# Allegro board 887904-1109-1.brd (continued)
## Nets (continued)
D20604: D206.04
D20605: D206.05
D20606: D206.06
D20607: D206.07
D20608: D206.08
D20609: D206.09
D20610: D206.10
D20611: D206.11
D20612: D206.12
D20613: D206.13
D20614: D206.14
D20615: D206.15
D20616: D206.16
D20701: D207.01
D20702: D207.02
D20703: D207.03
D20704: D207.04
D20705: D207.05
D20706: D207.06
D20707: D207.07
D20708: D207.08
D20709: D207.09
D20710: D207.10
D20711: D207.11
D20712: D207.12
D20713: D207.13
D20714: D207.14
D20715: D207.15
D20716: D207.16
D20801: D208.01
D20802: D208.02
D20803: D208.03
D20804: D208.04
D20805: D208.05
D20806: D208.06
D20807: D208.07
D20808: D208.08
D20809: D208.09
D20810: D208.10
D20811: D208.11
D20812: D208.12
D20813: D208.13
D20814: D208.14
D20815: D208.15
D20816: D208.16
D20901: D209.01
D20902: D209.02
D20903: D209.03
D20904: D209.04
D20905: D209.05
D20906: D209.06
D20907: D209.07
D20908: D209.08
D20909: D209.09
D20910: D209.10
D20911: D209.11
D20912: D209.12
D20913: D209.13
D20914: D209.14
D20915: D209.15
D20916: D209.16
D21001: D210.01
D21002: D210.02
D21003: D210.03
D21004: D210.04
D21005: D210.05
D21006: D210.06
D21007: D210.07
D21008: D210.08
D21009: D210.09
D21010: D210.10
D21011: D210.11
D21012: D210.12
D21013: D210.13
D21014: D210.14
D21015: D210.15
D21016: D210.16
D21101: D211.01
D21102: D211.02
D21103: D211.03
D21104: D211.04
D21105: D211.05
D21106: D211.06
D21107: D211.07
D21108: D211.08
D21109: D211.09
D21110: D211.10
D21111: D211.11
D21112: D211.12
D21113: D211.13
D21114: D211.14
D21115: D211.15
D21116: D211.16
D21201: D212.01
D21202: D212.02
D21203: D212.03
D21204: D212.04
D21205: D212.05
D21206: D212.06
D21207: D212.07
D21208: D212.08
D21209: D212.09
D21210: D212.10
D21211: D212.11
D21212: D212.12
D21213: D212.13
D21214: D212.14
D21215: D212.15
D21216: D212.16
D21301: D213.01
D21302: D213.02
D21303: D213.03
D21304: D213.04
D21305: D213.05
D21306: D213.06
D21307: D213.07
D21308: D213.08
D21309: D213.09
D21310: D213.10
D21311: D213.11
D21312: D213.12
D21313: D213.13
D21314: D213.14
D21315: D213.15
D21316: D213.16
D21401: D214.01
D21402: D214.02
D21403: D214.03
D21404: D214.04
D21405: D214.05
D21406: D214.06
D21407: D214.07
D21408: D214.08
D21409: D214.09
D21410: D214.10
D21411: D214.11
D21412: D214.12
D21413: D214.13
D21414: D214.14
D21415: D214.15
D21416: D214.16
D21501: D215.01
D21502: D215.02
D21503: D215.03
D21504: D215.04
D21505: D215.05
D21506: D215.06
D21507: D215.07
D21508: D215.08
D21509: D215.09
D21510: D215.10
D21511: D215.11
D21512: D215.12
D21513: D215.13
D21514: D215.14
D21515: D215.15
D21516: D215.16
D21601: D216.01
D21602: D216.02
D21603: D216.03
D21604: D216.04
D21605: D216.05
D21606: D216.06
D21607: D216.07
D21608: D216.08
D21609: D216.09
D21610: D216.10
D21611: D216.11
D21612: D216.12
D21613: D216.13
D21614: D216.14
D21615: D216.15
D21616: D216.16
D21701: D217.01
D21702: D217.02
D21703: D217.03
D21704: D217.04
D21705: D217.05
D21706: D217.06
D21707: D217.07
D21708: D217.08
D21709: D217.09
D21710: D217.10
D21711: D217.11
D21712: D217.12
D21713: D217.13
D21714: D217.14
D21715: D217.15
D21716: D217.16
D21801: D218.01
D21802: D218.02
D21803: D218.03
D21804: D218.04
D21805: D218.05
D21806: D218.06
D21807: D218.07
D21808: D218.08
D21809: D218.09
D21810: D218.10
D21811: D218.11
D21812: D218.12
D21813: D218.13
D21814: D218.14
D21815: D218.15
D21816: D218.16
D21901: D219.01
D21902: D219.02
D21903: D219.03
D21904: D219.04
D21905: D219.05
D21906: D219.06
D21907: D219.07
D21908: D219.08
D21909: D219.09
D21910: D219.10
D21911: D219.11
D21912: D219.12
D21913: D219.13
D21914: D219.14
D21915: D219.15
D21916: D219.16
D22001: D220.01
D22002: D220.02
D22003: D220.03
D22004: D220.04
D22005: D220.05
D22006: D220.06
D22007: D220.07
D22008: D220.08
D22009: D220.09
D22010: D220.10
D22011: D220.11
D22012: D220.12
D22013: D220.13
D22014: D220.14
D22015: D220.15
D22016: D220.16
D22101: D221.01
D22102: D221.02
D22103: D221.03
D22104: D221.04
D22105: D221.05
D22106: D221.06
D22107: D221.07
D22108: D221.08
D22109: D221.09
D22110: D221.10
D22111: D221.11
D22112: D221.12
D22113: D221.13
D22114: D221.14
D22115: D221.15
D22116: D221.16
D22201: D222.01
D22202: D222.02
D22203: D222.03
D22204: D222.04
D22205: D222.05
D22206: D222.06
D22207: D222.07
D22208: D222.08
D22209: D222.09
D22210: D222.10
D22211: D222.11
D22212: D222.12
D22213: D222.13
D22214: D222.14
D22215: D222.15
D22216: D222.16
D22301: D223.01
D22302: D223.02
D22303: D223.03
D22304: D223.04
D22305: D223.05
D22306: D223.06
D22307: D223.07
D22308: D223.08
D22309: D223.09
D22310: D223.10
D22311: D223.11
D22312: D223.12
D22313: D223.13
D22314: D223.14
D22315: D223.15
D22316: D223.16
D22401: D224.01
D22402: D224.02
D22403: D224.03
D22404: D224.04
D22405: D224.05
D22406: D224.06
D22407: D224.07
D22408: D224.08
D22409: D224.09
D22410: D224.10
D22411: D224.11
D22412: D224.12
D22413: D224.13
D22414: D224.14
D22415: D224.15
D22416: D224.16
D30101: D301.01
D30102: D301.02
D30103: D301.03
D30104: D301.04
D30105: D301.05
D30106: D301.06
D30107: D301.07
D30108: D301.08
D30109: D301.09
D30110: D301.10
D30111: D301.11
D30112: D301.12
D30113: D301.13
D30114: D301.14
D30115: D301.15
D30116: D301.16
D30201: D302.01
D30202: D302.02
D30203: D302.03
D30204: D302.04
D30205: D302.05
D30206: D302.06
D30207: D302.07
D30208: D302.08
D30209: D302.09
D30210: D302.10
D30211: D302.11
D30212: D302.12
D30213: D302.13
D30214: D302.14
D30215: D302.15
D30216: D302.16
D30501: D305.01
D30502: D305.02
D30503: D305.03
D30504: D305.04
D30505: D305.05
D30506: D305.06
D30507: D305.07
D30508: D305.08
D30509: D305.09
D30510: D305.10
D30511: D305.11
D30512: D305.12
D30513: D305.13
D30514: D305.14
D30515: D305.15
D30516: D305.16
D30601: D306.01
D30602: D306.02
D30603: D306.03
D30604: D306.04
D30605: D306.05
D30606: D306.06
D30607: D306.07
D30608: D306.08
D30609: D306.09
D30610: D306.10
D30611: D306.11
D30612: D306.12
D30613: D306.13
D30614: D306.14
D30615: D306.15
D30616: D306.16
D31701: D317.01
D31702: D317.02
D31703: D317.03
D31704: D317.04
D31705: D317.05
D31706: D317.06
D31707: D317.07
D31708: D317.08
D31709: D317.09
D31710: D317.10
D31711: D317.11
D31712: D317.12
D31713: D317.13
D31714: D317.14
D31715: D317.15
D31716: D317.16
D31801: D318.01
D31802: D318.02
D31803: D318.03
D31804: D318.04
D31805: D318.05
D31806: D318.06
D31807: D318.07
D31808: D318.08
D31809: D318.09
D31810: D318.10
D31811: D318.11
D31812: D318.12
D31813: D318.13
D31814: D318.14
D31815: D318.15
D31816: D318.16
D32101: D321.01
D32102: D321.02
D32103: D321.03
D32104: D321.04
D32105: D321.05
D32106: D321.06
D32107: D321.07
D32108: D321.08
D32109: D321.09
D32110: D321.10
D32111: D321.11
D32112: D321.12
D32113: D321.13
D32114: D321.14
D32115: D321.15
D32116: D321.16
D32201: D322.01
D32202: D322.02
D32203: D322.03
D32204: D322.04
D32205: D322.05
D32206: D322.06
D32207: D322.07
D32208: D322.08
D32209: D322.09
D32210: D322.10
D32211: D322.11
D32212: D322.12
D32213: D322.13
D32214: D322.14
D32215: D322.15
D32216: D322.16
DPS1_C1: DPS1.C01
DPS1_C5: DPS1.C05
DPS1_C11: DPS1.C11
DPS1_C15: DPS1.C15
DPS2_C1: DPS2.C01
DPS2_C5: DPS2.C05
DPS2_C11: DPS2.C11
DPS2_C15: DPS2.C15
DPS3_C1: DPS3.C01
DPS3_C5: DPS3.C05
DPS3_C11: DPS3.C11
DPS3_C15: DPS3.C15
DPS8_C1: DPS8.C01
DPS8_C5: DPS8.C05
DPS8_C11: DPS8.C11
DPS8_C15: DPS8.C15
MSDPS1_1F: DPS1.C03
MSDPS1_1GRD: DPS1.B02
MSDPS1_1GS: DPS1.A02
MSDPS1_1S: DPS1.C02
MSDPS1_2F: DPS1.C07
MSDPS1_2GRD: DPS1.B06
MSDPS1_2GS: DPS1.A06
MSDPS1_2S: DPS1.C06
MSDPS1_3F: DPS1.C13
MSDPS1_3GRD: DPS1.B12
MSDPS1_3GS: DPS1.A12
MSDPS1_3S: DPS1.C12
MSDPS1_4F: DPS1.C17
MSDPS1_4GRD: DPS1.B16
MSDPS1_4GS: DPS1.A16
MSDPS1_4S: DPS1.C16
MSDPS1_5F: DPS1.A03
MSDPS1_5GS: DPS1.B01
MSDPS1_5S: DPS1.B03
MSDPS1_6F: DPS1.A07
MSDPS1_6GS: DPS1.B05
MSDPS1_6S: DPS1.B07
MSDPS1_7F: DPS1.A13
MSDPS1_7GS: DPS1.B11
MSDPS1_7S: DPS1.B13
MSDPS1_8F: DPS1.A17
MSDPS1_8GS: DPS1.B15
MSDPS1_8S: DPS1.B17
MSDPS1_TR+: DPS1.A09 DPS2.A09 DPS3.A09 DPS8.A09 SB11.1
MSDPS1_TRVB-: DPS1.B09 SB1.2
MSDPS1_VB+: DPS1.C09 DPS2.C09 DPS3.C09 DPS8.C09 SB12.1
MSDPS2_1F: DPS2.C03
MSDPS2_1GRD: DPS2.B02
MSDPS2_1GS: DPS2.A02
MSDPS2_1S: DPS2.C02
MSDPS2_2F: DPS2.C07
MSDPS2_2GRD: DPS2.B06
MSDPS2_2GS: DPS2.A06
MSDPS2_2S: DPS2.C06
MSDPS2_3F: DPS2.C13
MSDPS2_3GRD: DPS2.B12
MSDPS2_3GS: DPS2.A12
MSDPS2_3S: DPS2.C12
MSDPS2_4F: DPS2.C17
MSDPS2_4GRD: DPS2.B16
MSDPS2_4GS: DPS2.A16
MSDPS2_4S: DPS2.C16
MSDPS2_5F: DPS2.A03
MSDPS2_5GS: DPS2.B01
MSDPS2_5S: DPS2.B03
MSDPS2_6F: DPS2.A07
MSDPS2_6GS: DPS2.B05
MSDPS2_6S: DPS2.B07
MSDPS2_7F: DPS2.A13
MSDPS2_7GS: DPS2.B11
MSDPS2_7S: DPS2.B13
MSDPS2_8F: DPS2.A17
MSDPS2_8GS: DPS2.B15
MSDPS2_8S: DPS2.B17
MSDPS2_TRVB-: DPS2.B09 SB2.2
MSDPS3_1F: DPS3.C03
MSDPS3_1GRD: DPS3.B02
MSDPS3_1GS: DPS3.A02
MSDPS3_1S: DPS3.C02
MSDPS3_2F: DPS3.C07
MSDPS3_2GRD: DPS3.B06
MSDPS3_2GS: DPS3.A06
MSDPS3_2S: DPS3.C06
MSDPS3_3F: DPS3.C13
MSDPS3_3GRD: DPS3.B12
MSDPS3_3GS: DPS3.A12
MSDPS3_3S: DPS3.C12
MSDPS3_4F: DPS3.C17
MSDPS3_4GRD: DPS3.B16
MSDPS3_4GS: DPS3.A16
MSDPS3_4S: DPS3.C16
MSDPS3_5F: DPS3.A03
MSDPS3_5GS: DPS3.B01
MSDPS3_5S: DPS3.B03
MSDPS3_6F: DPS3.A07
MSDPS3_6GS: DPS3.B05
MSDPS3_6S: DPS3.B07
MSDPS3_7F: DPS3.A13
MSDPS3_7GS: DPS3.B11
MSDPS3_7S: DPS3.B13
MSDPS3_8F: DPS3.A17
MSDPS3_8GS: DPS3.B15
MSDPS3_8S: DPS3.B17
MSDPS3_TRVB-: DPS3.B09 SB3.2
MSDPS8_1F: DPS8.C03
MSDPS8_1GRD: DPS8.B02
MSDPS8_1GS: DPS8.A02
MSDPS8_1S: DPS8.C02
MSDPS8_2F: DPS8.C07
MSDPS8_2GRD: DPS8.B06
MSDPS8_2GS: DPS8.A06
MSDPS8_2S: DPS8.C06
MSDPS8_3F: DPS8.C13
MSDPS8_3GRD: DPS8.B12
MSDPS8_3GS: DPS8.A12
MSDPS8_3S: DPS8.C12
MSDPS8_4F: DPS8.C17
MSDPS8_4GRD: DPS8.B16
MSDPS8_4GS: DPS8.A16
MSDPS8_4S: DPS8.C16
MSDPS8_5F: DPS8.A03
MSDPS8_5GS: DPS8.B01
MSDPS8_5S: DPS8.B03
MSDPS8_6F: DPS8.A07
MSDPS8_6GS: DPS8.B05
MSDPS8_6S: DPS8.B07
MSDPS8_7F: DPS8.A13
MSDPS8_7GS: DPS8.B11
MSDPS8_7S: DPS8.B13
MSDPS8_8F: DPS8.A17
MSDPS8_8GS: DPS8.B15
MSDPS8_8S: DPS8.B17
MSDPS8_TRVB-: DPS8.B09 SB8.2
S1_AUX1+: K9.5 R162.1
S1_AUX1-: K9.4 R161.1
S1_AUX2+: C54.2 R52.1 R54.2 R162.2
S1_AUX2-: C53.2 R51.2 R53.2 R161.2
S1_AUX+: K9.6 K50.6 SITE1.D14(AUX_P)
S1_AUX-: K9.3 K50.3 SITE1.E14(AUX_N)
S1_AUX_100DCH001+: K9.7
S1_AUX_100DCH001-: K9.2
S1_AUX_100DCH003+: C54.1
S1_AUX_100DCH003-: C53.1
S1_DCH005: SITE1.A14(HPD)
S1_DCH006: K10.3 SITE1.A1(RESET)
S1_DCH007: SITE1.B15(BIST)
S1_DCH009: SITE1.C15(CABC_EN)
S1_DCH010: SITE1.A15(PWMI)
S1_DCH011: SITE1.E3(PWMO)
S1_DCH012: K28.6 SITE1.C1(I2C_SDA)
S1_DCH013: K28.3 SITE1.D1(I2C_SCL)
S1_DCH014: K48.2
S1_DCH015: SITE1.E5(GPIO1)
S1_DCH016: SITE1.D5(GPIO2)
S1_DCH017: SITE1.D6(GPIO3)
S1_DCH018: SITE1.D7(GPIO4)
S1_DCH019: SITE1.D8(GPIO5)
S1_DCH020: SITE1.E6(GPIO6)
S1_DCH021: SITE1.D3(GPIO7)
S1_DCH022: SITE1.E4(GPIO8)
S1_DCH023: SITE1.C2(GPIO9)
S1_DCH024: SITE1.D15(GPIO10)
S1_DCH025: SITE1.B1(STV1)
S1_DCH026: SITE1.D2(STV2)
S1_DCH027: SITE1.B2(CPV)
S1_DCH028: SITE1.E1(OE1)
S1_DCH029: SITE1.E2(OE2)
S1_DCH030: SITE1.A3(XSTB)
S1_DCH031: SITE1.A2(SD_LOCK)
S1_DCH032: R200.2
S1_DCH033: R201.2
S1_DCH034: R202.2
S1_DCH035: R203.2
S1_DCH036: R204.2
S1_DCH037: R205.2
S1_DCH038: R206.2
S1_DCH039: R207.2
S1_DCH040: R208.2
S1_DCH041: R209.2
S1_DCH42: K15.2
S1_DCH43: K15.7
S1_DCH44: K14.2
S1_DCH45: K14.7
S1_DPS_F01: C67.1 CA1.1 CC1.1 CC2.1 CC3.1 CC4.1 CD1.1 CD2.1 CD3.1 CD4.1 K55.4 R200.1 SH1.2 SITE1.C4(VDD_CORE_09[1]) SITE1.C8(VDD_CORE_09[2]) SITE1.C9(VDD_CORE_09[3]) SITE1.C10(VDD_CORE_09[4]) TP_VDD09_CORE.1(TP)
S1_DPS_F03: C71.1 CA2.1 CC5.1 CC6.1 CC7.1 CD5.1 CD6.1 CD7.1 K56.4 R55.2 R201.1 SH3.2 SITE1.C5(VDD_IO_18[2]) SITE1.C6(VDD_IO_18[3]) SITE1.C11(VDD_IO_18[1]) TP_VDDIO_18.1(TP)
S1_DPS_F04: C73.1 CA3.1 CC8.1 CD8.1 K57.9 R202.1 SH6.2 SITE1.A5(VDD_TX_09_HDO) TP_VDD_TX_09_HDO.1(TP)
S1_DPS_F05: C75.1 CA4.1 CC9.1 CD9.1 K58.4 R203.1 SH7.2 SITE1.C7(VDD_TXPST_09) TP_VDD_TXPST_09.1(TP)
S1_DPS_F06: C77.1 CA5.1 CC10.1 CD10.1 K58.9 R204.1 SH10.2 SITE1.A4(VDD_TX_09) TP_VDD_TX_09.1(TP)
S1_DPS_F07: C79.1 CA6.1 CC11.1 CD11.1 K59.4 R205.1 SH12.2 SITE1.C14(VDDRX_AUX_09) TP_VDDRX_AUX.1(TP)
S1_DPS_F08: C81.1 CA7.1 CC12.1 CD12.1 K56.9 R206.1 SH14.2 SITE1.E15(VDDRX_09) TP_VDDRX_09.1(TP)
S1_DPS_F09: C83.1 CA8.1 CC13.1 CD13.1 K59.9 R207.1 SH16.2 SITE1.B3(VDD_PLL_09) TP_VDD_PLL_09.1(TP)
S1_DPS_F10: C85.1 CA9.1 CC14.1 CD14.1 K55.9 R208.1 SH18.2 SITE1.B14(VDD_IOB_18_BOOST) TP_VDD_IOB_18_BOOST.1(TP)
S1_DPS_F11: C87.1 CA10.1 CC15.1 CD15.1 K57.4 R209.1 SH20.2 SITE1.C3(VDD_IOB_18_POR) TP_VDD_IOB_18_POR.1(TP)
S1_DPS_F12: CA12.1 R52.2 R53.1 SH22.2 TP_S1_V25.1(TP)
S1_DPS_F13: CA13.1 K48.4 SH24.2 TP_VDD_EFUSE_POWER.1(TP)
S1_DPS_F14: C1.1 CA14.1 R69.1 R70.1 R71.1 R72.1 R73.1 R74.1 R147.2 R148.2 SH26.2 TP_VDD_EFUSE_POWER1.1(TP) U5.8(VCC)
S1_DPS_FS01: SH1.1
S1_DPS_FS03: SH3.1
S1_DPS_FS04: SH6.1
S1_DPS_FS05: SH7.1
S1_DPS_FS06: SH10.1
S1_DPS_FS07: SH12.1
S1_DPS_FS08: SH14.1
S1_DPS_FS09: SH16.1
S1_DPS_FS10: SH18.1
S1_DPS_FS11: SH20.1
S1_DPS_FS12: SH22.1
S1_DPS_FS13: SH24.1
S1_DPS_FS14: SH26.1
S1_DPS_GS01: SH2.1
S1_DPS_GS03: SH4.1
S1_DPS_GS04: SH5.1
S1_DPS_GS05: SH8.1
S1_DPS_GS06: SH9.1
S1_DPS_GS07: SH11.1
S1_DPS_GS08: SH13.1
S1_DPS_GS09: SH15.1
S1_DPS_GS10: SH17.1
S1_DPS_GS11: SH19.1
S1_DPS_GS12: SH21.1
S1_DPS_GS13: SH23.1
S1_DPS_GS14: SH25.1
S1_RLY01: K9.8(V-)
S1_RLY02: K50.8(V-)
S1_RLY03: K10.8(V-)
S1_RLY04: K48.8(V-)
S1_RLY08: K54.8(V-)
S1_RLY09: K61.8(V-)
S1_RLY20: K55.12(V-)
S1_RLY22: K57.12(V-)
S1_RLY24: K59.12(V-)
S1_RLY27: K15.8(V-)
S1_RLY43: K60.8(V-)
S1_RLY44: K62.8(V-)
S1_RLY45: K14.8(V-)
S1_RLY46: K28.8(V-)
S1_RLY47: K56.12(V-)
S1_RLY48: K58.12(V-)
S1_ROM_SPI_CS: K15.6 SITE1.E7(ROM_SPI_CS)
S1_ROM_SPI_SCK: K15.3 SITE1.E8(ROM_SPI_SCK)
S1_ROM_SPI_SDI: K14.6 SITE1.E9(ROM_SPI_SDI)
S1_ROM_SPI_SDO: K14.3 SITE1.D9(ROM_SPI_SDO)
S1_RX_85DCH00+: SITE1.E10(RX_N0)
S1_RX_85DCH00-: SITE1.D10(RX_P0)
S1_RX_85DCH01+: SITE1.E11(RX_N1)
S1_RX_85DCH01-: SITE1.D11(RX_P1)
S1_RX_85DCH02+: SITE1.D12(RX_N2)
S1_RX_85DCH02-: SITE1.E12(RX_P2)
S1_RX_85DCH03+: SITE1.D13(RX_N3)
S1_RX_85DCH03-: SITE1.E13(RX_P3)
S1_SPI_1_CSN: K15.5 R69.2 U5.1(CS#)
S1_SPI_1_SCK: K15.4 R73.2 U5.6(SCLK)
S1_SPI_1_SDI: K14.5 R70.2 U5.2(SO)
S1_SPI_1_SDO: K14.4 R74.2 U5.5(SI)
S1_TEST: K48.3 SITE1.D4(TEST)
S1_TX_100DCH0_N: R11.1 SITE1.A13(TX0_N)
S1_TX_100DCH0_P: R12.2 SITE1.B13(TX0_P)
S1_TX_100DCH1_N: R13.1 SITE1.B12(TX1_N)
S1_TX_100DCH1_P: R14.2 SITE1.A12(TX1_P)
S1_TX_100DCH2_N: R15.1 SITE1.B11(TX2_N)
S1_TX_100DCH2_P: R16.2 SITE1.A11(TX2_P)
S1_TX_100DCH3_N: R17.1 SITE1.B10(TX3_N)
S1_TX_100DCH3_P: R18.2 SITE1.A10(TX3_P)
S1_TX_100DCH4_N: R19.1 SITE1.A9(TX4_N)
S1_TX_100DCH4_P: R20.2 SITE1.B9(TX4_P)
S1_TX_100DCH5_N: R21.1 SITE1.A8(TX5_N)
S1_TX_100DCH5_P: R22.2 SITE1.B8(TX5_P)
S1_TX_100DCH6_N: R23.1 SITE1.A7(TX6_N)
S1_TX_100DCH6_P: R24.2 SITE1.B7(TX6_P)
S1_TX_100DCH7_N: R25.1 SITE1.B6(TX7_N)
S1_TX_100DCH7_P: R26.2 SITE1.A6(TX7_P)
S2_AUX1+: UNK2K9.5 UNK2R162.1
S2_AUX1-: UNK2K9.4 UNK2R161.1
S2_AUX2+: UNK2C54.2 UNK2R52.1 UNK2R54.2 UNK2R162.2
S2_AUX2-: UNK2C53.2 UNK2R51.2 UNK2R53.2 UNK2R161.2
S2_AUX+: SITE2.D14(AUX_P) UNK2K9.6 UNK2K50.6
S2_AUX-: SITE2.E14(AUX_N) UNK2K9.3 UNK2K50.3
S2_AUX_100DCH001+: UNK2K9.7
S2_AUX_100DCH001-: UNK2K9.2
S2_AUX_100DCH003+: UNK2C54.1
S2_AUX_100DCH003-: UNK2C53.1
S2_DCH005: SITE2.A14(HPD)
S2_DCH006: SITE2.A1(RESET) UNK2K10.3
S2_DCH007: SITE2.B15(BIST)
S2_DCH009: SITE2.C15(CABC_EN)
S2_DCH010: SITE2.A15(PWMI)
S2_DCH011: SITE2.E3(PWMO)
S2_DCH012: SITE2.C1(I2C_SDA) UNK2K28.6
S2_DCH013: SITE2.D1(I2C_SCL) UNK2K28.3
S2_DCH014: UNK2K48.2
S2_DCH015: SITE2.E5(GPIO1)
S2_DCH016: SITE2.D5(GPIO2)
S2_DCH017: SITE2.D6(GPIO3)
S2_DCH018: SITE2.D7(GPIO4)
S2_DCH019: SITE2.D8(GPIO5)
S2_DCH020: SITE2.E6(GPIO6)
S2_DCH021: SITE2.D3(GPIO7)
S2_DCH022: SITE2.E4(GPIO8)
S2_DCH023: SITE2.C2(GPIO9)
S2_DCH024: SITE2.D15(GPIO10)
S2_DCH025: SITE2.B1(STV1)
S2_DCH026: SITE2.D2(STV2)
S2_DCH027: SITE2.B2(CPV)
S2_DCH028: SITE2.E1(OE1)
S2_DCH029: SITE2.E2(OE2)
S2_DCH030: SITE2.A3(XSTB)
S2_DCH031: SITE2.A2(SD_LOCK)
S2_DCH032: UNK2R200.2
S2_DCH033: UNK2R201.2
S2_DCH034: UNK2R202.2
S2_DCH035: UNK2R203.2
S2_DCH036: UNK2R204.2
S2_DCH037: UNK2R205.2
S2_DCH038: UNK2R206.2
S2_DCH039: UNK2R207.2
S2_DCH040: UNK2R208.2
S2_DCH041: UNK2R209.2
S2_DCH42: UNK2K15.2
S2_DCH43: UNK2K15.7
S2_DCH44: UNK2K14.2
S2_DCH45: UNK2K14.7
S2_DPS_F01: SITE2.C4(VDD_CORE_09[1]) SITE2.C8(VDD_CORE_09[2]) SITE2.C9(VDD_CORE_09[3]) SITE2.C10(VDD_CORE_09[4]) UNK2C67.1 UNK2CA1.1 UNK2CC1.1 UNK2CC2.1 UNK2CC3.1 UNK2CC4.1 UNK2CD1.1 UNK2CD2.1 UNK2CD3.1 UNK2CD4.1 UNK2K55.4 UNK2R200.1 UNK2SH1.2 UNK2TP_VDD09_CORE.1
S2_DPS_F03: SITE2.C5(VDD_IO_18[2]) SITE2.C6(VDD_IO_18[3]) SITE2.C11(VDD_IO_18[1]) UNK2C71.1 UNK2CA2.1 UNK2CC5.1 UNK2CC6.1 UNK2CC7.1 UNK2CD5.1 UNK2CD6.1 UNK2CD7.1 UNK2K56.4 UNK2R55.2 UNK2R201.1 UNK2SH3.2 UNK2TP_VDDIO_18.1
S2_DPS_F04: SITE2.A5(VDD_TX_09_HDO) UNK2C73.1 UNK2CA3.1 UNK2CC8.1 UNK2CD8.1 UNK2K57.9 UNK2R202.1 UNK2SH6.2 UNK2TP_VDD_TX_09_HDO.1
S2_DPS_F05: SITE2.C7(VDD_TXPST_09) UNK2C75.1 UNK2CA4.1 UNK2CC9.1 UNK2CD9.1 UNK2K58.4 UNK2R203.1 UNK2SH7.2 UNK2TP_VDD_TXPST_09.1
S2_DPS_F06: SITE2.A4(VDD_TX_09) UNK2C77.1 UNK2CA5.1 UNK2CC10.1 UNK2CD10.1 UNK2K58.9 UNK2R204.1 UNK2SH10.2 UNK2TP_VDD_TX_09.1
S2_DPS_F07: SITE2.C14(VDDRX_AUX_09) UNK2C79.1 UNK2CA6.1 UNK2CC11.1 UNK2CD11.1 UNK2K59.4 UNK2R205.1 UNK2SH12.2 UNK2TP_VDDRX_AUX.1
S2_DPS_F08: SITE2.E15(VDDRX_09) UNK2C81.1 UNK2CA7.1 UNK2CC12.1 UNK2CD12.1 UNK2K56.9 UNK2R206.1 UNK2SH14.2 UNK2TP_VDDRX_09.1
S2_DPS_F09: SITE2.B3(VDD_PLL_09) UNK2C83.1 UNK2CA8.1 UNK2CC13.1 UNK2CD13.1 UNK2K59.9 UNK2R207.1 UNK2SH16.2 UNK2TP_VDD_PLL_09.1
S2_DPS_F10: SITE2.B14(VDD_IOB_18_BOOST) UNK2C85.1 UNK2CA9.1 UNK2CC14.1 UNK2CD14.1 UNK2K55.9 UNK2R208.1 UNK2SH18.2 UNK2TP_VDD_IOB_18_BOOST.1
S2_DPS_F11: SITE2.C3(VDD_IOB_18_POR) UNK2C87.1 UNK2CA10.1 UNK2CC15.1 UNK2CD15.1 UNK2K57.4 UNK2R209.1 UNK2SH20.2 UNK2TP_VDD_IOB_18_POR.1
S2_DPS_FS01: UNK2SH1.1
S2_DPS_FS03: UNK2SH3.1
S2_DPS_FS04: UNK2SH6.1
S2_DPS_FS05: UNK2SH7.1
S2_DPS_FS06: UNK2SH10.1
S2_DPS_FS07: UNK2SH12.1
S2_DPS_FS08: UNK2SH14.1
S2_DPS_FS09: UNK2SH16.1
S2_DPS_FS10: UNK2SH18.1
S2_DPS_FS11: UNK2SH20.1
S2_DPS_GS01: UNK2SH2.1
S2_DPS_GS03: UNK2SH4.1
S2_DPS_GS04: UNK2SH5.1
S2_DPS_GS05: UNK2SH8.1
S2_DPS_GS06: UNK2SH9.1
S2_DPS_GS07: UNK2SH11.1
S2_DPS_GS08: UNK2SH13.1
S2_DPS_GS09: UNK2SH15.1
S2_DPS_GS10: UNK2SH17.1
S2_DPS_GS11: UNK2SH19.1
S2_RLY01: UNK2K9.8
S2_RLY02: UNK2K50.8
S2_RLY03: UNK2K10.8
S2_RLY04: UNK2K48.8
S2_RLY08: UNK2K54.8
S2_RLY09: UNK2K61.8
S2_RLY20: UNK2K55.12
S2_RLY22: UNK2K57.12
S2_RLY24: UNK2K59.12
S2_RLY27: UNK2K15.8
S2_RLY43: UNK2K60.8
S2_RLY44: UNK2K62.8
S2_RLY45: UNK2K14.8
S2_RLY46: UNK2K28.8
S2_RLY47: UNK2K56.12
S2_RLY48: UNK2K58.12
S2_ROM_SPI_CS: SITE2.E7(ROM_SPI_CS) UNK2K15.6
S2_ROM_SPI_SCK: SITE2.E8(ROM_SPI_SCK) UNK2K15.3
S2_ROM_SPI_SDI: SITE2.E9(ROM_SPI_SDI) UNK2K14.6
S2_ROM_SPI_SDO: SITE2.D9(ROM_SPI_SDO) UNK2K14.3
S2_RX_85DCH00+: SITE2.E10(RX_N0)
S2_RX_85DCH00-: SITE2.D10(RX_P0)
S2_RX_85DCH01+: SITE2.E11(RX_N1)
S2_RX_85DCH01-: SITE2.D11(RX_P1)
S2_RX_85DCH02+: SITE2.D12(RX_N2)
S2_RX_85DCH02-: SITE2.E12(RX_P2)
S2_RX_85DCH03+: SITE2.D13(RX_N3)
S2_RX_85DCH03-: SITE2.E13(RX_P3)
S2_SPI_1_CSN: UNK2K15.5 UNK2R69.2 UNK2U5.1
S2_SPI_1_SCK: UNK2K15.4 UNK2R73.2 UNK2U5.6
S2_SPI_1_SDI: UNK2K14.5 UNK2R70.2 UNK2U5.2
S2_SPI_1_SDO: UNK2K14.4 UNK2R74.2 UNK2U5.5
S2_TEST: SITE2.D4(TEST) UNK2K48.3
S2_TX_100DCH0_N: SITE2.A13(TX0_N) UNK2R11.1
S2_TX_100DCH0_P: SITE2.B13(TX0_P) UNK2R12.2
S2_TX_100DCH1_N: SITE2.B12(TX1_N) UNK2R13.1
S2_TX_100DCH1_P: SITE2.A12(TX1_P) UNK2R14.2
S2_TX_100DCH2_N: SITE2.B11(TX2_N) UNK2R15.1
S2_TX_100DCH2_P: SITE2.A11(TX2_P) UNK2R16.2
S2_TX_100DCH3_N: SITE2.B10(TX3_N) UNK2R17.1
S2_TX_100DCH3_P: SITE2.A10(TX3_P) UNK2R18.2
S2_TX_100DCH4_N: SITE2.A9(TX4_N) UNK2R19.1
S2_TX_100DCH4_P: SITE2.B9(TX4_P) UNK2R20.2
S2_TX_100DCH5_N: SITE2.A8(TX5_N) UNK2R21.1
S2_TX_100DCH5_P: SITE2.B8(TX5_P) UNK2R22.2
S2_TX_100DCH6_N: SITE2.A7(TX6_N) UNK2R23.1
S2_TX_100DCH6_P: SITE2.B7(TX6_P) UNK2R24.2
S2_TX_100DCH7_N: SITE2.B6(TX7_N) UNK2R25.1
S2_TX_100DCH7_P: SITE2.A6(TX7_P) UNK2R26.2
S2_V25: UNK2R52.2 UNK2R53.1
S2_VCC_I2C_FLASH_18: UNK2C1.1 UNK2R69.1 UNK2R70.1 UNK2R71.1 UNK2R72.1 UNK2R73.1 UNK2R74.1 UNK2R147.2 UNK2R148.2 UNK2U5.8
S2_VDD_EFUSE_POWER: UNK2K48.4
S3_AUX1+: UNK3K9.5 UNK3R162.1
S3_AUX1-: UNK3K9.4 UNK3R161.1
S3_AUX2+: UNK3C54.2 UNK3R52.1 UNK3R54.2 UNK3R162.2
S3_AUX2-: UNK3C53.2 UNK3R51.2 UNK3R53.2 UNK3R161.2
S3_AUX+: SITE3.D14(AUX_P) UNK3K9.6 UNK3K50.6
S3_AUX-: SITE3.E14(AUX_N) UNK3K9.3 UNK3K50.3
S3_AUX_100DCH001+: UNK3K9.7
S3_AUX_100DCH001-: UNK3K9.2
S3_AUX_100DCH003+: UNK3C54.1
S3_AUX_100DCH003-: UNK3C53.1
S3_DCH005: SITE3.A14(HPD)
S3_DCH006: SITE3.A1(RESET) UNK3K10.3
S3_DCH007: SITE3.B15(BIST)
S3_DCH009: SITE3.C15(CABC_EN)
S3_DCH010: SITE3.A15(PWMI)
S3_DCH011: SITE3.E3(PWMO)
S3_DCH012: SITE3.C1(I2C_SDA) UNK3K28.6
S3_DCH013: SITE3.D1(I2C_SCL) UNK3K28.3
S3_DCH014: UNK3K48.2
S3_DCH015: SITE3.E5(GPIO1)
S3_DCH016: SITE3.D5(GPIO2)
S3_DCH017: SITE3.D6(GPIO3)
S3_DCH018: SITE3.D7(GPIO4)
S3_DCH019: SITE3.D8(GPIO5)
S3_DCH020: SITE3.E6(GPIO6)
S3_DCH021: SITE3.D3(GPIO7)
S3_DCH022: SITE3.E4(GPIO8)
S3_DCH023: SITE3.C2(GPIO9)
S3_DCH024: SITE3.D15(GPIO10)
S3_DCH025: SITE3.B1(STV1)
S3_DCH026: SITE3.D2(STV2)
S3_DCH027: SITE3.B2(CPV)
S3_DCH028: SITE3.E1(OE1)
S3_DCH029: SITE3.E2(OE2)
S3_DCH030: SITE3.A3(XSTB)
S3_DCH031: SITE3.A2(SD_LOCK)
S3_DCH032: UNK3R200.2
S3_DCH033: UNK3R201.2
S3_DCH034: UNK3R202.2
S3_DCH035: UNK3R203.2
S3_DCH036: UNK3R204.2
S3_DCH037: UNK3R205.2
S3_DCH038: UNK3R206.2
S3_DCH039: UNK3R207.2
S3_DCH040: UNK3R208.2
S3_DCH041: UNK3R209.2
S3_DCH42: UNK3K15.2
S3_DCH43: UNK3K15.7
S3_DCH44: UNK3K14.2
S3_DCH45: UNK3K14.7
S3_DPS_F01: SITE3.C4(VDD_CORE_09[1]) SITE3.C8(VDD_CORE_09[2]) SITE3.C9(VDD_CORE_09[3]) SITE3.C10(VDD_CORE_09[4]) UNK3C67.1 UNK3CA1.1 UNK3CC1.1 UNK3CC2.1 UNK3CC3.1 UNK3CC4.1 UNK3CD1.1 UNK3CD2.1 UNK3CD3.1 UNK3CD4.1 UNK3K55.4 UNK3R200.1 UNK3SH1.2 UNK3TP_VDD09_CORE.1
S3_DPS_F03: SITE3.C5(VDD_IO_18[2]) SITE3.C6(VDD_IO_18[3]) SITE3.C11(VDD_IO_18[1]) UNK3C71.1 UNK3CA2.1 UNK3CC5.1 UNK3CC6.1 UNK3CC7.1 UNK3CD5.1 UNK3CD6.1 UNK3CD7.1 UNK3K56.4 UNK3R55.2 UNK3R201.1 UNK3SH3.2 UNK3TP_VDDIO_18.1
S3_DPS_F04: SITE3.A5(VDD_TX_09_HDO) UNK3C73.1 UNK3CA3.1 UNK3CC8.1 UNK3CD8.1 UNK3K57.9 UNK3R202.1 UNK3SH6.2 UNK3TP_VDD_TX_09_HDO.1
S3_DPS_F05: SITE3.C7(VDD_TXPST_09) UNK3C75.1 UNK3CA4.1 UNK3CC9.1 UNK3CD9.1 UNK3K58.4 UNK3R203.1 UNK3SH7.2 UNK3TP_VDD_TXPST_09.1
S3_DPS_F06: SITE3.A4(VDD_TX_09) UNK3C77.1 UNK3CA5.1 UNK3CC10.1 UNK3CD10.1 UNK3K58.9 UNK3R204.1 UNK3SH10.2 UNK3TP_VDD_TX_09.1
S3_DPS_F07: SITE3.C14(VDDRX_AUX_09) UNK3C79.1 UNK3CA6.1 UNK3CC11.1 UNK3CD11.1 UNK3K59.4 UNK3R205.1 UNK3SH12.2 UNK3TP_VDDRX_AUX.1
S3_DPS_F08: SITE3.E15(VDDRX_09) UNK3C81.1 UNK3CA7.1 UNK3CC12.1 UNK3CD12.1 UNK3K56.9 UNK3R206.1 UNK3SH14.2 UNK3TP_VDDRX_09.1
S3_DPS_F09: SITE3.B3(VDD_PLL_09) UNK3C83.1 UNK3CA8.1 UNK3CC13.1 UNK3CD13.1 UNK3K59.9 UNK3R207.1 UNK3SH16.2 UNK3TP_VDD_PLL_09.1
S3_DPS_F10: SITE3.B14(VDD_IOB_18_BOOST) UNK3C85.1 UNK3CA9.1 UNK3CC14.1 UNK3CD14.1 UNK3K55.9 UNK3R208.1 UNK3SH18.2 UNK3TP_VDD_IOB_18_BOOST.1
S3_DPS_F11: SITE3.C3(VDD_IOB_18_POR) UNK3C87.1 UNK3CA10.1 UNK3CC15.1 UNK3CD15.1 UNK3K57.4 UNK3R209.1 UNK3SH20.2 UNK3TP_VDD_IOB_18_POR.1
S3_DPS_FS01: UNK3SH1.1
S3_DPS_FS03: UNK3SH3.1
S3_DPS_FS04: UNK3SH6.1
S3_DPS_FS05: UNK3SH7.1
S3_DPS_FS06: UNK3SH10.1
S3_DPS_FS07: UNK3SH12.1
S3_DPS_FS08: UNK3SH14.1
S3_DPS_FS09: UNK3SH16.1
S3_DPS_FS10: UNK3SH18.1
S3_DPS_FS11: UNK3SH20.1
S3_DPS_GS01: UNK3SH2.1
S3_DPS_GS03: UNK3SH4.1
S3_DPS_GS04: UNK3SH5.1
S3_DPS_GS05: UNK3SH8.1
S3_DPS_GS06: UNK3SH9.1
S3_DPS_GS07: UNK3SH11.1
S3_DPS_GS08: UNK3SH13.1
S3_DPS_GS09: UNK3SH15.1
S3_DPS_GS10: UNK3SH17.1
S3_DPS_GS11: UNK3SH19.1
S3_RLY01: UNK3K9.8
S3_RLY02: UNK3K50.8
S3_RLY03: UNK3K10.8
S3_RLY04: UNK3K48.8
S3_RLY08: UNK3K54.8
S3_RLY09: UNK3K61.8
S3_RLY20: UNK3K55.12
S3_RLY22: UNK3K57.12
S3_RLY24: UNK3K59.12
S3_RLY27: UNK3K15.8
S3_RLY43: UNK3K60.8
S3_RLY44: UNK3K62.8
S3_RLY45: UNK3K14.8
S3_RLY46: UNK3K28.8
S3_RLY47: UNK3K56.12
S3_RLY48: UNK3K58.12
S3_ROM_SPI_CS: SITE3.E7(ROM_SPI_CS) UNK3K15.6
S3_ROM_SPI_SCK: SITE3.E8(ROM_SPI_SCK) UNK3K15.3
S3_ROM_SPI_SDI: SITE3.E9(ROM_SPI_SDI) UNK3K14.6
S3_ROM_SPI_SDO: SITE3.D9(ROM_SPI_SDO) UNK3K14.3
S3_RX_85DCH00+: SITE3.E10(RX_N0)
S3_RX_85DCH00-: SITE3.D10(RX_P0)
S3_RX_85DCH01+: SITE3.E11(RX_N1)
S3_RX_85DCH01-: SITE3.D11(RX_P1)
S3_RX_85DCH02+: SITE3.D12(RX_N2)
S3_RX_85DCH02-: SITE3.E12(RX_P2)
S3_RX_85DCH03+: SITE3.D13(RX_N3)
S3_RX_85DCH03-: SITE3.E13(RX_P3)
S3_SPI_1_CSN: UNK3K15.5 UNK3R69.2 UNK3U5.1
S3_SPI_1_SCK: UNK3K15.4 UNK3R73.2 UNK3U5.6
S3_SPI_1_SDI: UNK3K14.5 UNK3R70.2 UNK3U5.2
S3_SPI_1_SDO: UNK3K14.4 UNK3R74.2 UNK3U5.5
S3_TEST: SITE3.D4(TEST) UNK3K48.3
S3_TX_100DCH0_N: SITE3.A13(TX0_N) UNK3R11.1
S3_TX_100DCH0_P: SITE3.B13(TX0_P) UNK3R12.2
S3_TX_100DCH1_N: SITE3.B12(TX1_N) UNK3R13.1
S3_TX_100DCH1_P: SITE3.A12(TX1_P) UNK3R14.2
S3_TX_100DCH2_N: SITE3.B11(TX2_N) UNK3R15.1
S3_TX_100DCH2_P: SITE3.A11(TX2_P) UNK3R16.2
S3_TX_100DCH3_N: SITE3.B10(TX3_N) UNK3R17.1
S3_TX_100DCH3_P: SITE3.A10(TX3_P) UNK3R18.2
S3_TX_100DCH4_N: SITE3.A9(TX4_N) UNK3R19.1
S3_TX_100DCH4_P: SITE3.B9(TX4_P) UNK3R20.2
S3_TX_100DCH5_N: SITE3.A8(TX5_N) UNK3R21.1
S3_TX_100DCH5_P: SITE3.B8(TX5_P) UNK3R22.2
S3_TX_100DCH6_N: SITE3.A7(TX6_N) UNK3R23.1
S3_TX_100DCH6_P: SITE3.B7(TX6_P) UNK3R24.2
S3_TX_100DCH7_N: SITE3.B6(TX7_N) UNK3R25.1
S3_TX_100DCH7_P: SITE3.A6(TX7_P) UNK3R26.2
S3_V25: UNK3R52.2 UNK3R53.1
S3_VCC_I2C_FLASH_18: UNK3C1.1 UNK3R69.1 UNK3R70.1 UNK3R71.1 UNK3R72.1 UNK3R73.1 UNK3R74.1 UNK3R147.2 UNK3R148.2 UNK3U5.8
S3_VDD_EFUSE_POWER: UNK3K48.4
S4_AUX1+: UNK4K9.5 UNK4R162.1
S4_AUX1-: UNK4K9.4 UNK4R161.1
S4_AUX2+: UNK4C54.2 UNK4R52.1 UNK4R54.2 UNK4R162.2
S4_AUX2-: UNK4C53.2 UNK4R51.2 UNK4R53.2 UNK4R161.2
S4_AUX+: SITE4.D14(AUX_P) UNK4K9.6 UNK4K50.6
S4_AUX-: SITE4.E14(AUX_N) UNK4K9.3 UNK4K50.3
S4_AUX_100DCH001+: UNK4K9.7
S4_AUX_100DCH001-: UNK4K9.2
S4_AUX_100DCH003+: UNK4C54.1
S4_AUX_100DCH003-: UNK4C53.1
S4_DCH005: SITE4.A14(HPD)
S4_DCH006: SITE4.A1(RESET) UNK4K10.3
S4_DCH007: SITE4.B15(BIST)
S4_DCH009: SITE4.C15(CABC_EN)
S4_DCH010: SITE4.A15(PWMI)
S4_DCH011: SITE4.E3(PWMO)
S4_DCH012: SITE4.C1(I2C_SDA) UNK4K28.6
S4_DCH013: SITE4.D1(I2C_SCL) UNK4K28.3
S4_DCH014: UNK4K48.2
S4_DCH015: SITE4.E5(GPIO1)
S4_DCH016: SITE4.D5(GPIO2)
S4_DCH017: SITE4.D6(GPIO3)
S4_DCH018: SITE4.D7(GPIO4)
S4_DCH019: SITE4.D8(GPIO5)
S4_DCH020: SITE4.E6(GPIO6)
S4_DCH021: SITE4.D3(GPIO7)
S4_DCH022: SITE4.E4(GPIO8)
S4_DCH023: SITE4.C2(GPIO9)
S4_DCH024: SITE4.D15(GPIO10)
S4_DCH025: SITE4.B1(STV1)
S4_DCH026: SITE4.D2(STV2)
S4_DCH027: SITE4.B2(CPV)
S4_DCH028: SITE4.E1(OE1)
S4_DCH029: SITE4.E2(OE2)
S4_DCH030: SITE4.A3(XSTB)
S4_DCH031: SITE4.A2(SD_LOCK)
S4_DCH032: UNK4R200.2
S4_DCH033: UNK4R201.2
S4_DCH034: UNK4R202.2
S4_DCH035: UNK4R203.2
S4_DCH036: UNK4R204.2
S4_DCH037: UNK4R205.2
S4_DCH038: UNK4R206.2
S4_DCH039: UNK4R207.2
S4_DCH040: UNK4R208.2
S4_DCH041: UNK4R209.2
S4_DCH42: UNK4K15.2
S4_DCH43: UNK4K15.7
S4_DCH44: UNK4K14.2
S4_DCH45: UNK4K14.7
S4_DPS_F01: SITE4.C4(VDD_CORE_09[1]) SITE4.C8(VDD_CORE_09[2]) SITE4.C9(VDD_CORE_09[3]) SITE4.C10(VDD_CORE_09[4]) UNK4C67.1 UNK4CA1.1 UNK4CC1.1 UNK4CC2.1 UNK4CC3.1 UNK4CC4.1 UNK4CD1.1 UNK4CD2.1 UNK4CD3.1 UNK4CD4.1 UNK4K55.4 UNK4R200.1 UNK4SH1.2 UNK4TP_VDD09_CORE.1
S4_DPS_F03: SITE4.C5(VDD_IO_18[2]) SITE4.C6(VDD_IO_18[3]) SITE4.C11(VDD_IO_18[1]) UNK4C71.1 UNK4CA2.1 UNK4CC5.1 UNK4CC6.1 UNK4CC7.1 UNK4CD5.1 UNK4CD6.1 UNK4CD7.1 UNK4K56.4 UNK4R55.2 UNK4R201.1 UNK4SH3.2 UNK4TP_VDDIO_18.1
S4_DPS_F04: SITE4.A5(VDD_TX_09_HDO) UNK4C73.1 UNK4CA3.1 UNK4CC8.1 UNK4CD8.1 UNK4K57.9 UNK4R202.1 UNK4SH6.2 UNK4TP_VDD_TX_09_HDO.1
S4_DPS_F05: SITE4.C7(VDD_TXPST_09) UNK4C75.1 UNK4CA4.1 UNK4CC9.1 UNK4CD9.1 UNK4K58.4 UNK4R203.1 UNK4SH7.2 UNK4TP_VDD_TXPST_09.1
S4_DPS_F06: SITE4.A4(VDD_TX_09) UNK4C77.1 UNK4CA5.1 UNK4CC10.1 UNK4CD10.1 UNK4K58.9 UNK4R204.1 UNK4SH10.2 UNK4TP_VDD_TX_09.1
S4_DPS_F07: SITE4.C14(VDDRX_AUX_09) UNK4C79.1 UNK4CA6.1 UNK4CC11.1 UNK4CD11.1 UNK4K59.4 UNK4R205.1 UNK4SH12.2 UNK4TP_VDDRX_AUX.1
S4_DPS_F08: SITE4.E15(VDDRX_09) UNK4C81.1 UNK4CA7.1 UNK4CC12.1 UNK4CD12.1 UNK4K56.9 UNK4R206.1 UNK4SH14.2 UNK4TP_VDDRX_09.1
S4_DPS_F09: SITE4.B3(VDD_PLL_09) UNK4C83.1 UNK4CA8.1 UNK4CC13.1 UNK4CD13.1 UNK4K59.9 UNK4R207.1 UNK4SH16.2 UNK4TP_VDD_PLL_09.1
S4_DPS_F10: SITE4.B14(VDD_IOB_18_BOOST) UNK4C85.1 UNK4CA9.1 UNK4CC14.1 UNK4CD14.1 UNK4K55.9 UNK4R208.1 UNK4SH18.2 UNK4TP_VDD_IOB_18_BOOST.1
S4_DPS_F11: SITE4.C3(VDD_IOB_18_POR) UNK4C87.1 UNK4CA10.1 UNK4CC15.1 UNK4CD15.1 UNK4K57.4 UNK4R209.1 UNK4SH20.2 UNK4TP_VDD_IOB_18_POR.1
S4_DPS_FS01: UNK4SH1.1
S4_DPS_FS03: UNK4SH3.1
S4_DPS_FS04: UNK4SH6.1
S4_DPS_FS05: UNK4SH7.1
S4_DPS_FS06: UNK4SH10.1
S4_DPS_FS07: UNK4SH12.1
S4_DPS_FS08: UNK4SH14.1
S4_DPS_FS09: UNK4SH16.1
S4_DPS_FS10: UNK4SH18.1
S4_DPS_FS11: UNK4SH20.1
S4_DPS_GS01: UNK4SH2.1
S4_DPS_GS03: UNK4SH4.1
S4_DPS_GS04: UNK4SH5.1
S4_DPS_GS05: UNK4SH8.1
S4_DPS_GS06: UNK4SH9.1
S4_DPS_GS07: UNK4SH11.1
S4_DPS_GS08: UNK4SH13.1
S4_DPS_GS09: UNK4SH15.1
S4_DPS_GS10: UNK4SH17.1
S4_DPS_GS11: UNK4SH19.1
S4_RLY01: UNK4K9.8
S4_RLY02: UNK4K50.8
S4_RLY03: UNK4K10.8
S4_RLY04: UNK4K48.8
S4_RLY08: UNK4K54.8
S4_RLY09: UNK4K61.8
S4_RLY20: UNK4K55.12
S4_RLY22: UNK4K57.12
S4_RLY24: UNK4K59.12
S4_RLY27: UNK4K15.8
S4_RLY43: UNK4K60.8
S4_RLY44: UNK4K62.8
S4_RLY45: UNK4K14.8
S4_RLY46: UNK4K28.8
S4_RLY47: UNK4K56.12
S4_RLY48: UNK4K58.12
S4_ROM_SPI_CS: SITE4.E7(ROM_SPI_CS) UNK4K15.6
S4_ROM_SPI_SCK: SITE4.E8(ROM_SPI_SCK) UNK4K15.3
S4_ROM_SPI_SDI: SITE4.E9(ROM_SPI_SDI) UNK4K14.6
S4_ROM_SPI_SDO: SITE4.D9(ROM_SPI_SDO) UNK4K14.3
S4_RX_85DCH00+: SITE4.E10(RX_N0)
S4_RX_85DCH00-: SITE4.D10(RX_P0)
S4_RX_85DCH01+: SITE4.E11(RX_N1)
S4_RX_85DCH01-: SITE4.D11(RX_P1)
S4_RX_85DCH02+: SITE4.D12(RX_N2)
S4_RX_85DCH02-: SITE4.E12(RX_P2)
S4_RX_85DCH03+: SITE4.D13(RX_N3)
S4_RX_85DCH03-: SITE4.E13(RX_P3)
S4_SPI_1_CSN: UNK4K15.5 UNK4R69.2 UNK4U5.1
S4_SPI_1_SCK: UNK4K15.4 UNK4R73.2 UNK4U5.6
S4_SPI_1_SDI: UNK4K14.5 UNK4R70.2 UNK4U5.2
S4_SPI_1_SDO: UNK4K14.4 UNK4R74.2 UNK4U5.5
S4_TEST: SITE4.D4(TEST) UNK4K48.3
S4_TX_100DCH0_N: SITE4.A13(TX0_N) UNK4R11.1
S4_TX_100DCH0_P: SITE4.B13(TX0_P) UNK4R12.2
S4_TX_100DCH1_N: SITE4.B12(TX1_N) UNK4R13.1
S4_TX_100DCH1_P: SITE4.A12(TX1_P) UNK4R14.2
S4_TX_100DCH2_N: SITE4.B11(TX2_N) UNK4R15.1
S4_TX_100DCH2_P: SITE4.A11(TX2_P) UNK4R16.2
S4_TX_100DCH3_N: SITE4.B10(TX3_N) UNK4R17.1
S4_TX_100DCH3_P: SITE4.A10(TX3_P) UNK4R18.2
S4_TX_100DCH4_N: SITE4.A9(TX4_N) UNK4R19.1
S4_TX_100DCH4_P: SITE4.B9(TX4_P) UNK4R20.2
S4_TX_100DCH5_N: SITE4.A8(TX5_N) UNK4R21.1
S4_TX_100DCH5_P: SITE4.B8(TX5_P) UNK4R22.2
S4_TX_100DCH6_N: SITE4.A7(TX6_N) UNK4R23.1
S4_TX_100DCH6_P: SITE4.B7(TX6_P) UNK4R24.2
S4_TX_100DCH7_N: SITE4.B6(TX7_N) UNK4R25.1
S4_TX_100DCH7_P: SITE4.A6(TX7_P) UNK4R26.2
S4_V25: UNK4R52.2 UNK4R53.1
S4_VCC_I2C_FLASH_18: UNK4C1.1 UNK4R69.1 UNK4R70.1 UNK4R71.1 UNK4R72.1 UNK4R73.1 UNK4R74.1 UNK4R147.2 UNK4R148.2 UNK4U5.8
S4_VDD_EFUSE_POWER: UNK4K48.4
UDBGND: BD29.2 BD30.2 BD31.2 BD32.2 BD33.2 BD34.2 BD35.2 BD36.2 BD37.2 BD38.2 BD39.2 BD40.2 BD41.2 BD42.2 BD43.2 BD44.2 CB1.2 CB2.1 CB3.2 CB4.1 CB5.2 CB6.1 CB7.2 CB8.1 CB9.2 CB10.2 CB11.2 CB12.2 CB13.2 CB14.2 CB15.2 CB16.2 CB19.2 LDB1.2(B) UB1.1(NC) UB1.2(A1/NC) UB1.3(A2) UB1.4(GND) UB1.7(WP) UTL1.A02 UTL1.A08 UTL1.A10 UTL1.A12 UTL1.A14 UTL1.B01 UTL1.B07 UTL1.B09 UTL1.B11 UTL1.B13 UTL2.A02 UTL2.A08 UTL2.A10 UTL2.A12 UTL2.A14 UTL2.B01 UTL2.B07 UTL2.B09 UTL2.B11 UTL2.B13 UTL3.A02 UTL3.A08 UTL3.A10 UTL3.A12 UTL3.A14 UTL3.B01 UTL3.B07 UTL3.B09 UTL3.B11 UTL3.B13 UTL4.A02 UTL4.A08 UTL4.A10 UTL4.A12 UTL4.A14 UTL4.B01 UTL4.B07 UTL4.B09 UTL4.B11 UTL4.B13 UTL5.A02 UTL5.A08 UTL5.A10 UTL5.A12 UTL5.A14 UTL5.B01 UTL5.B07 UTL5.B09 UTL5.B11 UTL5.B13 UTL6.A02 UTL6.A08 UTL6.A10 UTL6.A12 UTL6.A14 UTL6.B01 UTL6.B07 UTL6.B09 UTL6.B11 UTL6.B13 UTL7.A02 UTL7.A08 UTL7.A10 UTL7.A12 UTL7.A14 UTL7.B01 UTL7.B07 UTL7.B09 UTL7.B11 UTL7.B13 UTL8.A02 UTL8.A08 UTL8.A10 UTL8.A12 UTL8.A14 UTL8.B01 UTL8.B07 UTL8.B09 UTL8.B11 UTL8.B13
UT1_PDCF: UTL1.B15
UT1_PDCS: UTL1.A15
UT1_PGDS: UTL1.A16
UT1_PGRD: UTL1.B16
UT1_UP5V: CB1.1 CB2.2 CB3.1 CB4.2 CB5.1 CB6.2 CB7.1 CB8.2 CB9.1 CB10.1 CB11.1 CB12.1 CB13.1 CB14.1 CB15.1 CB16.1 CB19.1 K9.1(V+) K10.1(V+) K14.1(V+) K15.1(V+) K28.1(V+) K48.1(V+) K50.1(V+) K54.1(V+) K55.1(V+) K56.1(V+) K57.1(V+) K58.1(V+) K59.1(V+) K60.1(V+) K61.1(V+) K62.1(V+) LRB1.1 RB1.1 RB2.1 UB1.8(VCC) UNK2K9.1 UNK2K10.1 UNK2K14.1 UNK2K15.1 UNK2K28.1 UNK2K48.1 UNK2K50.1 UNK2K54.1 UNK2K55.1 UNK2K56.1 UNK2K57.1 UNK2K58.1 UNK2K59.1 UNK2K60.1 UNK2K61.1 UNK2K62.1 UNK3K9.1 UNK3K10.1 UNK3K14.1 UNK3K15.1 UNK3K28.1 UNK3K48.1 UNK3K50.1 UNK3K54.1 UNK3K55.1 UNK3K56.1 UNK3K57.1 UNK3K58.1 UNK3K59.1 UNK3K60.1 UNK3K61.1 UNK3K62.1 UNK4K9.1 UNK4K10.1 UNK4K14.1 UNK4K15.1 UNK4K28.1 UNK4K48.1 UNK4K50.1 UNK4K54.1 UNK4K55.1 UNK4K56.1 UNK4K57.1 UNK4K58.1 UNK4K59.1 UNK4K60.1 UNK4K61.1 UNK4K62.1 UT_UP5V.1(TP) UTL1.A05 UTL1.B04 UTL2.A05 UTL2.B04 UTL3.A05 UTL3.B04 UTL4.A05 UTL4.B04 UTL5.A05 UTL5.B04 UTL6.A05 UTL6.B04 UTL7.A05 UTL7.B04 UTL8.A05 UTL8.B04
UT1_URW00: UTL1.A01
UT1_URW01: UTL1.B02
UT1_URW02: UTL1.A03
UT1_URW03: UTL1.B03
UT1_URW04: UTL1.A04
UT1_URW05: UTL1.B05
UT1_URW06: UTL1.A06
UT1_UW07: UTL1.B06
UT1_UW08: UTL1.A07
UT1_UW09: UTL1.B08
UT1_UW10: UTL1.A09
UT1_UW11: UTL1.B10
UT1_UW12: UTL1.A11
UT1_UW13: UTL1.B12
UT1_UW14: RB1.2 UB1.6(SCL) UTL1.A13
UT1_UW15: RB2.2 UB1.5(SDA) UTL1.B14
UT2_PDCF: UTL2.B15
UT2_PDCS: UTL2.A15
UT2_PGDS: UTL2.A16
UT2_PGRD: UTL2.B16
UT2_URW00: UTL2.A01
UT2_URW01: UTL2.B02
UT2_URW02: UTL2.A03
UT2_URW03: UTL2.B03
UT2_URW04: UTL2.A04
UT2_URW05: UTL2.B05
UT2_URW06: UTL2.A06
UT2_UW07: UTL2.B06
UT2_UW08: UTL2.A07
UT2_UW09: UTL2.B08
UT2_UW10: UTL2.A09
UT2_UW11: UTL2.B10
UT2_UW12: UTL2.A11
UT2_UW13: UTL2.B12
UT2_UW14: UTL2.A13
UT2_UW15: UTL2.B14
UT3_PDCF: UTL3.B15
UT3_PDCS: UTL3.A15
UT3_PGDS: UTL3.A16
UT3_PGRD: UTL3.B16
UT3_URW00: UTL3.A01
UT3_URW01: UTL3.B02
UT3_URW02: UTL3.A03
UT3_URW03: UTL3.B03
UT3_URW04: UTL3.A04
UT3_URW05: UTL3.B05
UT3_URW06: UTL3.A06
UT3_UW07: UTL3.B06
UT3_UW08: UTL3.A07
UT3_UW09: UTL3.B08
UT3_UW10: UTL3.A09
UT3_UW11: UTL3.B10
UT3_UW12: UTL3.A11
UT3_UW13: UTL3.B12
UT3_UW14: UTL3.A13
UT3_UW15: UTL3.B14
UT4_PDCF: UTL4.B15
UT4_PDCS: UTL4.A15
UT4_PGDS: UTL4.A16
UT4_PGRD: UTL4.B16
UT4_URW00: UTL4.A01
UT4_URW01: UTL4.B02
UT4_URW02: UTL4.A03
UT4_URW03: UTL4.B03
UT4_URW04: UTL4.A04
UT4_URW05: UTL4.B05
UT4_URW06: UTL4.A06
UT4_UW07: UTL4.B06
UT4_UW08: UTL4.A07
UT4_UW09: UTL4.B08
UT4_UW10: UTL4.A09
UT4_UW11: UTL4.B10
UT4_UW12: UTL4.A11
UT4_UW13: UTL4.B12
UT4_UW14: UTL4.A13
UT4_UW15: UTL4.B14
UT5_PDCF: UTL5.B15
UT5_PDCS: UTL5.A15
UT5_PGDS: UTL5.A16
UT5_PGRD: UTL5.B16
UT5_UW00: UTL5.A01
UT5_UW01: UTL5.B02
UT5_UW02: UTL5.A03
UT5_UW03: UTL5.B03
UT5_UW04: UTL5.A04
UT5_UW05: UTL5.B05
UT5_UW06: UTL5.A06
UT5_UW07: UTL5.B06
UT5_UW08: UTL5.A07
UT5_UW09: UTL5.B08
UT5_UW10: UTL5.A09
UT5_UW11: UTL5.B10
UT5_UW12: UTL5.A11
UT5_UW13: UTL5.B12
UT5_UW14: UTL5.A13
UT5_UW15: UTL5.B14
UT6_PDCF: UTL6.B15
UT6_PDCS: UTL6.A15
UT6_PGDS: UTL6.A16
UT6_PGRD: UTL6.B16
UT6_UW00: UTL6.A01
UT6_UW01: UTL6.B02
UT6_UW02: UTL6.A03
UT6_UW03: UTL6.B03
UT6_UW04: UTL6.A04
UT6_UW05: UTL6.B05
UT6_UW06: UTL6.A06
UT6_UW07: UTL6.B06
UT6_UW08: UTL6.A07
UT6_UW09: UTL6.B08
UT6_UW10: UTL6.A09
UT6_UW11: UTL6.B10
UT6_UW12: UTL6.A11
UT6_UW13: UTL6.B12
UT6_UW14: UTL6.A13
UT6_UW15: UTL6.B14
UT7_PDCF: UTL7.B15
UT7_PDCS: UTL7.A15
UT7_PGDS: UTL7.A16
UT7_PGRD: UTL7.B16
UT7_UW00: UTL7.A01
UT7_UW01: UTL7.B02
UT7_UW02: UTL7.A03
UT7_UW03: UTL7.B03
UT7_UW04: UTL7.A04
UT7_UW05: UTL7.B05
UT7_UW06: UTL7.A06
UT7_UW07: UTL7.B06
UT7_UW08: UTL7.A07
UT7_UW09: UTL7.B08
UT7_UW10: UTL7.A09
UT7_UW11: UTL7.B10
UT7_UW12: UTL7.A11
UT7_UW13: UTL7.B12
UT7_UW14: UTL7.A13
UT7_UW15: UTL7.B14
UT8_PDCF: UTL8.B15
UT8_PDCS: UTL8.A15
UT8_PGDS: UTL8.A16
UT8_PGRD: UTL8.B16
UT8_UW00: UTL8.A01
UT8_UW01: UTL8.B02
UT8_UW02: UTL8.A03
UT8_UW03: UTL8.B03
UT8_UW04: UTL8.A04
UT8_UW05: UTL8.B05
UT8_UW06: UTL8.A06
UT8_UW07: UTL8.B06
UT8_UW08: UTL8.A07
UT8_UW09: UTL8.B08
UT8_UW10: UTL8.A09
UT8_UW11: UTL8.B10
UT8_UW12: UTL8.A11
UT8_UW13: UTL8.B12
UT8_UW14: UTL8.A13
UT8_UW15: UTL8.B14
N18382758: K10.4 R55.1 SW1.1
N18409210: K61.5 R22.1
N18409215: K61.6 R21.2
N18409217: K61.4 R20.1
N18409219: K61.3 R19.2
N18409246: K54.5 R14.1
N18409248: K54.6 R13.2
N18409250: K54.4 R12.1
N18409252: K54.3 R11.2
N18409257: K60.5 R18.1
N18409273: K60.3 R15.2
N18409275: K60.4 R16.1
N18409277: K60.6 R17.2
N18409282: K62.5 R26.1
N18409298: K62.3 R23.2
N18409300: K62.4 R24.1
N18409302: K62.6 R25.2
N18431358: C69.1 K55.5
N18431428: C70.1 K55.8
N18446682: C89.1 K56.5
N18446702: C90.1 K56.8
N18446941: C91.1 K57.5
N18446958: C92.1 K57.8
N18447198: C93.1 K58.5
N18447215: C94.1 K58.8
N18451749: C95.1 K59.5
N18451764: C96.1 K59.8
N18709887: C55.2 SW1.2
N18876028: K28.4 R147.1
N18876030: K28.5 R148.1
N18954388: K50.4 R184.1
N18954392: K50.5 R185.1
N19199259: UNK2K10.4 UNK2R55.1 UNK2SW1.1
N19199302: UNK2K61.5 UNK2R22.1
N19199304: UNK2K61.6 UNK2R21.2
N19199305: UNK2K61.4 UNK2R20.1
N19199306: UNK2K61.3 UNK2R19.2
N19199318: UNK2K54.5 UNK2R14.1
N19199319: UNK2K54.6 UNK2R13.2
N19199320: UNK2K54.4 UNK2R12.1
N19199321: UNK2K54.3 UNK2R11.2
N19199323: UNK2K60.5 UNK2R18.1
N19199330: UNK2K60.3 UNK2R15.2
N19199331: UNK2K60.4 UNK2R16.1
N19199332: UNK2K60.6 UNK2R17.2
N19199334: UNK2K62.5 UNK2R26.1
N19199341: UNK2K62.3 UNK2R23.2
N19199342: UNK2K62.4 UNK2R24.1
N19199343: UNK2K62.6 UNK2R25.2
N19199463: UNK2C55.2 UNK2SW1.2
N19199473: UNK2K50.4 UNK2R184.1
N19199475: UNK2K50.5 UNK2R185.1
N19200862: UNK2R71.2 UNK2R163.2 UNK2U5.3
N19200865: UNK2R72.2 UNK2U5.7
N19200913: UNK2K28.4 UNK2R147.1
N19200914: UNK2K28.5 UNK2R148.1
N19201316: UNK2C69.1 UNK2K55.5
N19201318: UNK2C70.1 UNK2K55.8
N19201556: UNK2C89.1 UNK2K56.5
N19201559: UNK2C90.1 UNK2K56.8
N19201562: UNK2C91.1 UNK2K57.5
N19201565: UNK2C92.1 UNK2K57.8
N19201568: UNK2C93.1 UNK2K58.5
N19201571: UNK2C94.1 UNK2K58.8
N19201581: UNK2C95.1 UNK2K59.5
N19201583: UNK2C96.1 UNK2K59.8
N19203612: UNK3K10.4 UNK3R55.1 UNK3SW1.1
N19203655: UNK3K61.5 UNK3R22.1
N19203657: UNK3K61.6 UNK3R21.2
N19203658: UNK3K61.4 UNK3R20.1
N19203659: UNK3K61.3 UNK3R19.2
N19203671: UNK3K54.5 UNK3R14.1
N19203672: UNK3K54.6 UNK3R13.2
N19203673: UNK3K54.4 UNK3R12.1
N19203674: UNK3K54.3 UNK3R11.2
N19203676: UNK3K60.5 UNK3R18.1
N19203683: UNK3K60.3 UNK3R15.2
N19203684: UNK3K60.4 UNK3R16.1
N19203685: UNK3K60.6 UNK3R17.2
N19203687: UNK3K62.5 UNK3R26.1
N19203694: UNK3K62.3 UNK3R23.2
N19203695: UNK3K62.4 UNK3R24.1
N19203696: UNK3K62.6 UNK3R25.2
N19203816: UNK3C55.2 UNK3SW1.2
N19203826: UNK3K50.4 UNK3R184.1
N19203828: UNK3K50.5 UNK3R185.1
N19205215: UNK3R71.2 UNK3R163.2 UNK3U5.3
N19205218: UNK3R72.2 UNK3U5.7
N19205266: UNK3K28.4 UNK3R147.1
N19205267: UNK3K28.5 UNK3R148.1
N19205669: UNK3C69.1 UNK3K55.5
N19205671: UNK3C70.1 UNK3K55.8
N19205909: UNK3C89.1 UNK3K56.5
N19205912: UNK3C90.1 UNK3K56.8
N19205915: UNK3C91.1 UNK3K57.5
N19205918: UNK3C92.1 UNK3K57.8
N19205921: UNK3C93.1 UNK3K58.5
N19205924: UNK3C94.1 UNK3K58.8
N19205934: UNK3C95.1 UNK3K59.5
N19205936: UNK3C96.1 UNK3K59.8
N19207965: UNK4K10.4 UNK4R55.1 UNK4SW1.1
N19208008: UNK4K61.5 UNK4R22.1
N19208010: UNK4K61.6 UNK4R21.2
N19208011: UNK4K61.4 UNK4R20.1
N19208012: UNK4K61.3 UNK4R19.2
N19208024: UNK4K54.5 UNK4R14.1
N19208025: UNK4K54.6 UNK4R13.2
N19208026: UNK4K54.4 UNK4R12.1
N19208027: UNK4K54.3 UNK4R11.2
N19208029: UNK4K60.5 UNK4R18.1
N19208036: UNK4K60.3 UNK4R15.2
N19208037: UNK4K60.4 UNK4R16.1
N19208038: UNK4K60.6 UNK4R17.2
N19208040: UNK4K62.5 UNK4R26.1
N19208047: UNK4K62.3 UNK4R23.2
N19208048: UNK4K62.4 UNK4R24.1
N19208049: UNK4K62.6 UNK4R25.2
N19208169: UNK4C55.2 UNK4SW1.2
N19208179: UNK4K50.4 UNK4R184.1
N19208181: UNK4K50.5 UNK4R185.1
N19209568: UNK4R71.2 UNK4R163.2 UNK4U5.3
N19209571: UNK4R72.2 UNK4U5.7
N19209619: UNK4K28.4 UNK4R147.1
N19209620: UNK4K28.5 UNK4R148.1
N19210022: UNK4C69.1 UNK4K55.5
N19210024: UNK4C70.1 UNK4K55.8
N19210262: UNK4C89.1 UNK4K56.5
N19210265: UNK4C90.1 UNK4K56.8
N19210268: UNK4C91.1 UNK4K57.5
N19210271: UNK4C92.1 UNK4K57.8
N19210274: UNK4C93.1 UNK4K58.5
N19210277: UNK4C94.1 UNK4K58.8
N19210287: UNK4C95.1 UNK4K59.5
N19210289: UNK4C96.1 UNK4K59.8
N19277459: D431.09
N19277463: D431.02
N19277465: D431.01
N19277467: D431.06
N19277469: D431.05
N19277679: D431.10
N19277685: D431.11
N19277687: D431.12
N19277691: D431.13
N19277695: D431.14
N19277699: D431.15
N19277703: D431.04
N19277709: D431.03
N19277713: D431.07
N19277715: D431.08
N19277723: D431.16
N19277727: D431.17
N21639620: R71.2 R163.2 U5.3(WP#)
N21639626: R72.2 U5.7(HOLD#)
N21654412: LDB1.1(A) LRB1.2

Pads without a net: CSDPS225 A17 B17 C17 D17; CSDPS229 A17 B17 C17 D17; CSDPS425 A17 B17 C17 D17; CSDPS429 A17 B17 C17 D17; D101/D501 A1 A2 A3 A4 A5 A6 A7 A8 A9 A10 A11 A12 A13 A14 A15 A16 A17 B1 B2 B3 B4 B5 B6 B7 B8 B9 B10 B11 B12 B13 B14 B15 B16 B17 C1 C2 C3 C4 C5 C6 C7 C8 C9 C10 C11 C12 C13 C14 C15 C16 C17 D2 D3 D4 D5 D6 D7 D8 D9 D10 D11 D12 D13 D14 D15 D16; D102/D502 A1 A2 A3 A4 A5 A6 A7 A8 A9 A10 A11 A12 A13 A14 A15 A16 A17 B1 B2 B3 B4 B5 B6 B7 B8 B9 B10 B11 B12 B13 B14 B15 B16 B17 C1 C2 C3 C4 C5 C6 C7 C8 C9 C10 C11 C12 C13 C14 C15 C16 C17 D2 D3 D4 D5 D6 D7 D8 D9 D10 D11 D12 D13 D14 D15 D16; D103/D503 A1 A2 A3 A4 A5 A6 A7 A8 A9 A10 A11 A12 A13 A14 A15 A16 A17 B1 B2 B3 B4 B5 B6 B7 B8 B9 B10 B11 B12 B13 B14 B15 B16 B17 C1 C2 C3 C4 C5 C6 C7 C8 C9 C10 C11 C12 C13 C14 C15 C16 C17 D2 D3 D4 D5 D6 D7 D8 D9 D10 D11 D12 D13 D14 D15 D16; D104 17 A17 B17; D105/D505 A1 A2 A3 A4 A5 A6 A7 A8 A9 A10 A11 A12 A13 A14 A15 A16 A17 B1 B2 B3 B4 B5 B6 B7 B8 B9 B10 B11 B12 B13 B14 B15 B16 B17 C1 C2 C3 C4 C5 C6 C7 C8 C9 C10 C11 C12 C13 C14 C15 C16 C17 D2 D3 D4 D5 D6 D7 D8 D9 D10 D11 D12 D13 D14 D15 D16; D106/D506 A1 A2 A3 A4 A5 A6 A7 A8 A9 A10 A11 A12 A13 A14 A15 A16 A17 B1 B2 B3 B4 B5 B6 B7 B8 B9 B10 B11 B12 B13 B14 B15 B16 B17 C1 C2 C3 C4 C5 C6 C7 C8 C9 C10 C11 C12 C13 C14 C15 C16 C17 D2 D3 D4 D5 D6 D7 D8 D9 D10 D11 D12 D13 D14 D15 D16; D107/D507 A1 A2 A3 A4 A5 A6 A7 A8 A9 A10 A11 A12 A13 A14 A15 A16 A17 B1 B2 B3 B4 B5 B6 B7 B8 B9 B10 B11 B12 B13 B14 B15 B16 B17 C1 C2 C3 C4 C5 C6 C7 C8 C9 C10 C11 C12 C13 C14 C15 C16 C17 D2 D3 D4 D5 D6 D7 D8 D9 D10 D11 D12 D13 D14 D15 D16; D108 17 A17 B17; D109 17 A17 B17; D110 17 A17 B17; D111 17 A17 B17; D112 17 A17 B17; D113 17 A17 B17; D114 17 A17 B17; D115 17 A17 B17; D116 17 A17 B17; D117/D517 A1 A2 A3 A4 A5 A6 A7 A8 A9 A10 A11 A12 A13 A14 A15 A16 A17 B1 B2 B3 B4 B5 B6 B7 B8 B9 B10 B11 B12 B13 B14 B15 B16 B17 C1 C2 C3 C4 C5 C6 C7 C8 C9 C10 C11 C12 C13 C14 C15 C16 C17 D2 D3 D4 D5 D6 D7 D8 D9 D10 D11 D12 D13 D14 D15 D16; D118/D518 A1 A2 A3 A4 A5 A6 A7 A8 A9 A10 A11 A12 A13 A14 A15 A16 A17 B1 B2 B3 B4 B5 B6 B7 B8 B9 B10 B11 B12 B13 B14 B15 B16 B17 C1 C2 C3 C4 C5 C6 C7 C8 C9 C10 C11 C12 C13 C14 C15 C16 C17 D2 D3 D4 D5 D6 D7 D8 D9 D10 D11 D12 D13 D14 D15 D16; D119/D519 A1 A2 A3 A4 A5 A6 A7 A8 A9 A10 A11 A12 A13 A14 A15 A16 A17 B1 B2 B3 B4 B5 B6 B7 B8 B9 B10 B11 B12 B13 B14 B15 B16 B17 C1 C2 C3 C4 C5 C6 C7 C8 C9 C10 C11 C12 C13 C14 C15 C16 C17 D2 D3 D4 D5 D6 D7 D8 D9 D10 D11 D12 D13 D14 D15 D16; D120 17 A17 B17; D121/D521 A1 A2 A3 A4 A5 A6 A7 A8 A9 A10 A11 A12 A13 A14 A15 A16 A17 B1 B2 B3 B4 B5 B6 B7 B8 B9 B10 B11 B12 B13 B14 B15 B16 B17 C1 C2 C3 C4 C5 C6 C7 C8 C9 C10 C11 C12 C13 C14 C15 C16 C17 D2 D3 D4 D5 D6 D7 D8 D9 D10 D11 D12 D13 D14 D15 D16; D122/D522 A1 A2 A3 A4 A5 A6 A7 A8 A9 A10 A11 A12 A13 A14 A15 A16 A17 B1 B2 B3 B4 B5 B6 B7 B8 B9 B10 B11 B12 B13 B14 B15 B16 B17 C1 C2 C3 C4 C5 C6 C7 C8 C9 C10 C11 C12 C13 C14 C15 C16 C17 D2 D3 D4 D5 D6 D7 D8 D9 D10 D11 D12 D13 D14 D15 D16; D123/D523 A1 A2 A3 A4 A5 A6 A7 A8 A9 A10 A11 A12 A13 A14 A15 A16 A17 B1 B2 B3 B4 B5 B6 B7 B8 B9 B10 B11 B12 B13 B14 B15 B16 B17 C1 C2 C3 C4 C5 C6 C7 C8 C9 C10 C11 C12 C13 C14 C15 C16 C17 D2 D3 D4 D5 D6 D7 D8 D9 D10 D11 D12 D13 D14 D15 D16; D124 17 A17 B17; D125 17 A17 B17; D126 17 A17 B17; D127 17 A17 B17; D128 17 A17 B17; D129 17 A17 B17; D130 17 A17 B17; D131 17 A17 B17; D132 17 A17 B17; D201 17 A17 B17; D202 17 A17 B17; D203 17 A17 B17; D204 17 A17 B17; D205 17 A17 B17; D206 17 A17 B17; D207 17 A17 B17; D208 17 A17 B17; D209 17 A17 B17; D210 17 A17 B17; D211 17 A17 B17; D212 17 A17 B17; D213 17 A17 B17; D214 17 A17 B17; D215 17 A17 B17; D216 17 A17 B17; D217 17 A17 B17; D218 17 A17 B17; D219 17 A17 B17; D220 17 A17 B17; D221 17 A17 B17; D222 17 A17 B17; D223 17 A17 B17; D224 17 A17 B17; D301 17 A17 B17; D302 17 A17 B17; D305 17 A17 B17; D306 17 A17 B17; D317 17 A17 B17; D318 17 A17 B17; D321 17 A17 B17; D322 17 A17 B17; DPS1 A04 A08 A10 A14 B04 B08 B10 B14 C04 C08 C10 C14; DPS2 A04 A08 A10 A14 B04 B08 B10 B14 C04 C08 C10 C14; DPS3 A04 A08 A10 A14 B04 B08 B10 B14 C04 C08 C10 C14; DPS4 A02 A03 A04 A06 A07 A08 A09 A10 A12 A13 A14 A16 A17 B01 B02 B03 B04 B05 B06 B07 B08 B09 B10 B11 B12 B13 B14 B15 B16 B17 C02 C03 C04 C06 C07 C08 C09 C10 C12 C13 C14 C16 C17; DPS5 A02 A03 A04 A06 A07 A08 A09 A10 A12 A13 A14 A16 A17 B01 B02 B03 B04 B05 B06 B07 B08 B09 B10 B11 B12 B13 B14 B15 B16 B17 C02 C03 C04 C06 C07 C08 C09 C10 C12 C13 C14 C16 C17; DPS8 A04 A08 A10 A14 B04 B08 B10 B14 C04 C08 C10 C14; FD1 1; FD2 1; FD3 1; FD4 1; FD5 1; FD6 1; FD7 1; FD8 1; FD9 1; FD10 1; FD11 1; FD12 1; FD13 1; FD14 1; FD15 1; FD16 1; HX8879-F04 1; K10 2 5 6 7; K28 2 7; K48 5 6 7; K50 2 7; K54 2 7; K55 3 10; K56 3 10; K57 3 10; K58 3 10; K59 3 10; K60 2 7; K61 2 7; K62 2 7; LOGO1 1; LOGO2 1; SITE1 NUT1 NUT2 NUT3 NUT4; SITE2 NUT1 NUT2 NUT3 NUT4; SITE3 NUT1 NUT2 NUT3 NUT4; SITE4 NUT1 NUT2 NUT3 NUT4; SKB1 NUT1 NUT2 NUT3 NUT4; TPL1 1; TPL2 1; TPL3 1; TPL4 1; TPL5 1; TPL6 1; TPL7 1; TPL8 1; TPL9 1; TPL10 1; TPL11 1; TPL12 1; TPL13 1; TPL14 1; TPL15 1; TPL16 1; UF1 1; UNK2K10 2 5 6 7; UNK2K28 2 7; UNK2K48 5 6 7; UNK2K50 2 7; UNK2K54 2 7; UNK2K55 3 10; UNK2K56 3 10; UNK2K57 3 10; UNK2K58 3 10; UNK2K59 3 10; UNK2K60 2 7; UNK2K61 2 7; UNK2K62 2 7; UNK2UF1 1; UNK3K10 2 5 6 7; UNK3K28 2 7; UNK3K48 5 6 7; UNK3K50 2 7; UNK3K54 2 7; UNK3K55 3 10; UNK3K56 3 10; UNK3K57 3 10; UNK3K58 3 10; UNK3K59 3 10; UNK3K60 2 7; UNK3K61 2 7; UNK3K62 2 7; UNK3UF1 1; UNK4K10 2 5 6 7; UNK4K28 2 7; UNK4K48 5 6 7; UNK4K50 2 7; UNK4K54 2 7; UNK4K55 3 10; UNK4K56 3 10; UNK4K57 3 10; UNK4K58 3 10; UNK4K59 3 10; UNK4K60 2 7; UNK4K61 2 7; UNK4K62 2 7; UNK4UF1 1; UNK038HX-887904K4Q-A100 1; UNK980HX-887904-KAG- 1; UNK261103AA031 1; UTL1 A17 B17; UTL2 A17 B17; UTL3 A17 B17; UTL4 A17 B17; UTL5 A17 B17; UTL6 A17 B17; UTL7 A17 B17; UTL8 A17 B17; WFBGA-10X3.5X0.636-P0.65 1

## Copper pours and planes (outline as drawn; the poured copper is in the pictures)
GND on L02_GND: 302.07,1.02 290.83,6.67 279.59,1.02 1.02,1.02 1.02,428.24 205.93,428.24 217.17,422.59 228.41,428.24 353.25,428.24 364.49,422.59 375.73,428.24 580.64,428.24 580.64,1.02
